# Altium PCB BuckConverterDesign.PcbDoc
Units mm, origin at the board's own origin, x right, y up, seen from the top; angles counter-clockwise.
Board outline 71.7 x 34.6 mm, 4 copper layers (Top Layer, IN-1, IN-2, Bottom Layer), stack 0.603 mm thick; 48 components, 33 nets, 182 pads, 54 vias.
Unrouted connection lines stored in the file: 113.
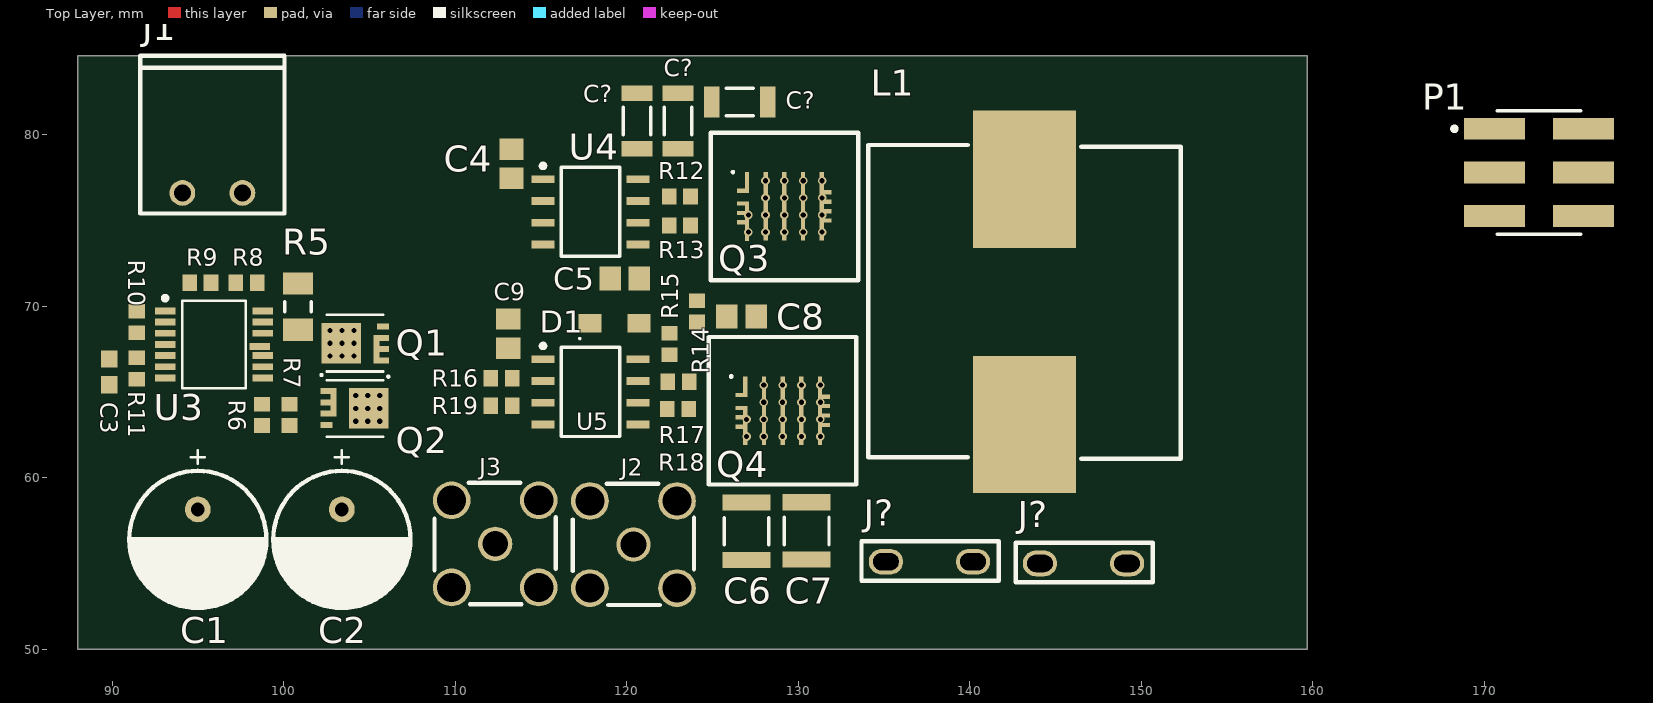
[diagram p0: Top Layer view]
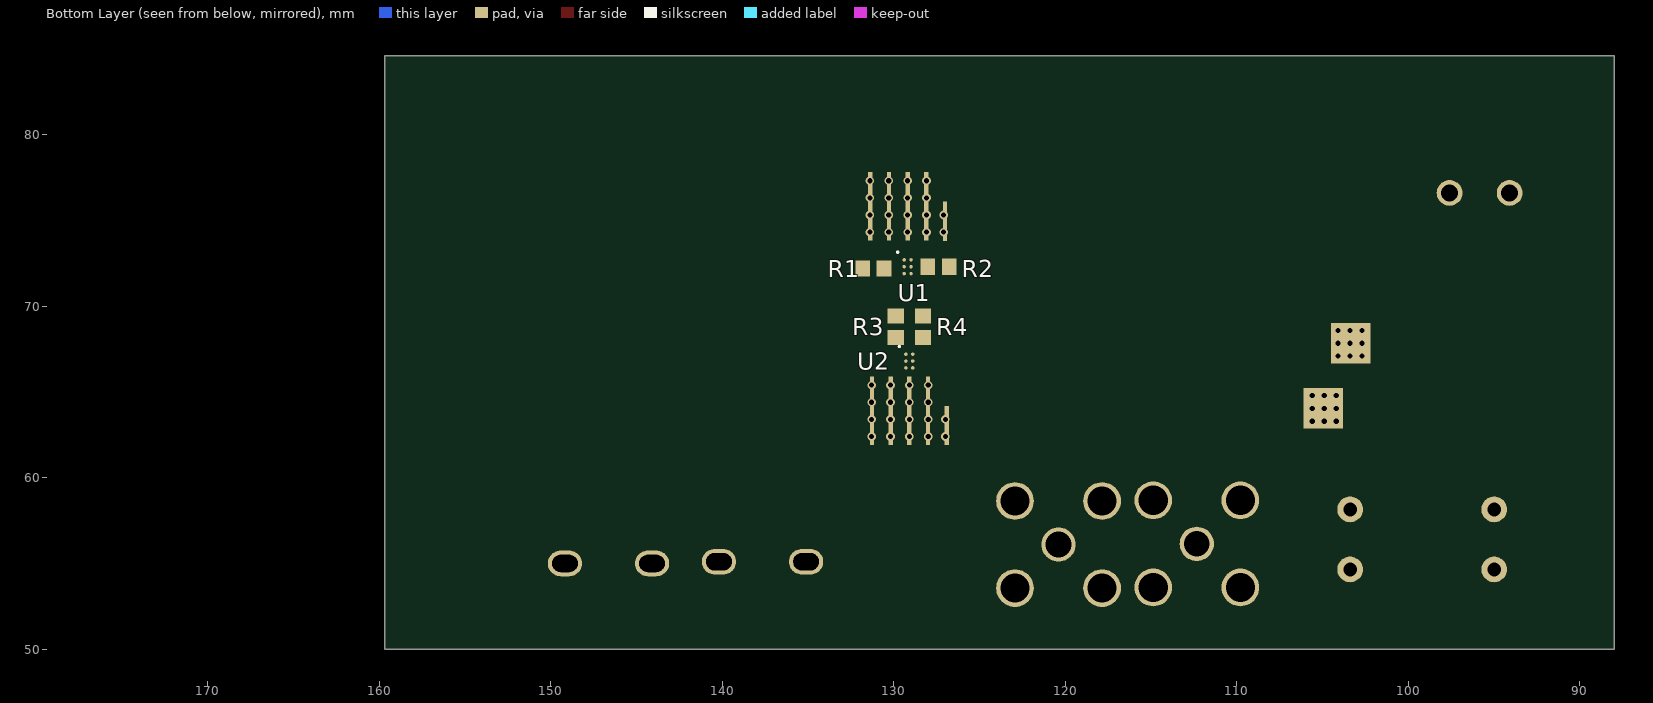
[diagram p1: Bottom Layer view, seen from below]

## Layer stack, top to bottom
Top Solder: solder mask 0.0102, Solder Resist, Dk 3.5
Top Layer: signal copper 0.035
Dielectric 2: prepreg 0.0711, PP-006, Dk 4.1
IN-1: signal copper 0.0356
Dielectric 1: dielectric 0.32, FR-4, Dk 4.8
IN-2: signal copper 0.0356
Dielectric 3: prepreg 0.0711, PP-006, Dk 4.1
Bottom Layer: signal copper 0.035
Bottom Solder: solder mask 0.0102, Solder Resist, Dk 3.5

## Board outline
88,50 159.7,50 159.7,84.6 88,84.6

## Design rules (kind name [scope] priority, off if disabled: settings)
AssemblyTestPointUsage [All] p1: isadvanced=TRUE
AssemblyTestpoint [All] p1: isadvanced=TRUE testpointundercomponent=TRUE minsize=1.016 maxsize=2.54 preferedsize=1.524 minholesize=0 maxholesize=1.016 preferedholesize=0.813 testpointgrid=0.025 usegrid=TRUE gridtolerance=0 allowsidetop=TRUE allowsidebottom=TRUE
Clearance Clearance_1 [All] p1: isadvanced=TRUE gap=0.15 ignorepadtopadclearanceinfootprint=FALSE
Clearance [All] p2: gap=0.254 ignorepadtopadclearanceinfootprint=FALSE ismatrix=TRUE
ComponentClearance [All] p1: isadvanced=TRUE gap=0.254 collisioncheckmode=3 verticalgap=0.254 showdistances=FALSE
FabricationTestPointUsage [All] p1: isadvanced=TRUE valid=0 allowmultiple=FALSE
FabricationTestpoint [All] p1: isadvanced=TRUE side=3 testpointundercomponent=TRUE minsize=1.016 maxsize=2.54 preferedsize=1.524 minholesize=0 maxholesize=1.016 preferedholesize=0.813 testpointgrid=0.025 allowsidetop=TRUE allowsidebottom=TRUE usegrid=TRUE gridtolerance=0
FanoutControl Fanout_BGA [IsBGA] p1: isadvanced=TRUE bgadir=Out bgaviamode=Centered fanoutstyle=Auto fanoutdirection=Alternating viagrid=0.025 // Fanout_BGA (Default Rule)
FanoutControl Fanout_LCC [IsLCC] p2: isadvanced=TRUE bgadir=Out bgaviamode=Centered fanoutstyle=Auto fanoutdirection=Alternating viagrid=0.025 // Fanout_LCC (Default Rule)
FanoutControl Fanout_SOIC [IsSOIC] p3: isadvanced=TRUE bgadir=Out bgaviamode=Centered fanoutstyle=Auto fanoutdirection=Alternating viagrid=0.025 // Fanout_SOIC (Default Rule)
FanoutControl Fanout_Small [(CompPinCount < 5)] p4: isadvanced=TRUE bgadir=Out bgaviamode=Centered fanoutstyle=Auto fanoutdirection=OutThenIn viagrid=0.025 // Fanout_Small (Default Rule)
FanoutControl Fanout_Default [All] p5: isadvanced=TRUE bgadir=Out bgaviamode=Centered fanoutstyle=Auto fanoutdirection=Alternating viagrid=0.025 // Fanout_Default (Default Rule)
Height [All] p1: isadvanced=TRUE minheight=0 maxheight=25.4 prefheight=12.7
HoleSize [All] p1: isadvanced=TRUE absolutevalues=TRUE maxlimit=20 minlimit=0.3 maxpercent=80.000 minpercent=20.000
HoleToHoleClearance [All] p1: isadvanced=TRUE gap=0.3 allowstackedmicrovias=TRUE
LayerPairs [All] p1: isadvanced=TRUE enforce=TRUE
MinimumSolderMaskSliver [All] p1: isadvanced=TRUE minsoldermaskwidth=0.15
NetAntennae [All] p1: isadvanced=TRUE netantennaetolerance=0
PasteMaskExpansion [All] p1: isadvanced=TRUE expansion=0.1 thpadusetoppaste=TRUE thpadusebottompaste=TRUE
PlaneClearance [All] p1: isadvanced=TRUE clearance=0.508
PlaneConnect [All] p1: isadvanced=TRUE planeconnectstyle=Relief reliefexpansion=0.508 reliefentries=4 reliefconductorwidth=0.254 reliefairgap=0.254
PolygonConnect PolygonConnect_5 [All vs IsNamedPolygon('SW_NODE_L01_P000')] p1: connectstyle=Direct reliefconductorwidth=0.254 reliefentries=4 polygonreliefangle="90 Angle" airgapwidth=0.254
PolygonConnect PolygonConnect_4 [All vs IsNamedPolygon('SW_NODE_L01_P000')] p2: connectstyle=Direct reliefconductorwidth=0.254 reliefentries=4 polygonreliefangle="90 Angle" airgapwidth=0.254
PolygonConnect PolygonConnect_3 [All vs IsNamedPolygon('NONET_L01_P000')] p3: thpad.connectstyle=Direct thpad.reliefconductorwidth=0.254 thpad.reliefentries=4 thpad.polygonreliefangle="90 Angle" thpad.airgapwidth=0.254 smdpad.connectstyle=Direct smdpad.reliefconductorwidth=0.254 smdpad.reliefentries=4 smdpad.polygonreliefangle="90 Angle" smdpad.airgapwidth=0.254 via.connectstyle=Relief via.reliefconductorwidth=0.254 via.reliefentries=4 via.polygonreliefangle="90 Angle" via.airgapwidth=0.254
PolygonConnect PolygonConnect_2 [All vs IsNamedPolygon('NONET_L01_P000')] p4: thpad.connectstyle=Direct thpad.reliefconductorwidth=0.254 thpad.reliefentries=4 thpad.polygonreliefangle="90 Angle" thpad.airgapwidth=0.254 smdpad.connectstyle=Direct smdpad.reliefconductorwidth=0.254 smdpad.reliefentries=4 smdpad.polygonreliefangle="90 Angle" smdpad.airgapwidth=0.254 via.connectstyle=Relief via.reliefconductorwidth=0.254 via.reliefentries=4 via.polygonreliefangle="90 Angle" via.airgapwidth=0.254
PolygonConnect PolygonConnect_1 [All vs IsNamedPolygon('NETQ3_1_L01_P001') Or IsNamedPolygon('NETQ4_1_L01_P002') Or IsNamedPolygon('NONET_L01_P000')] p5: connectstyle=Direct reliefconductorwidth=0.254 reliefentries=4 polygonreliefangle="90 Angle" airgapwidth=0.254
PolygonConnect [All] p6: connectstyle=Relief reliefconductorwidth=0.254 reliefentries=4 polygonreliefangle="90 Angle" airgapwidth=0.254
RoutingCorners [All] p1: isadvanced=TRUE cornerstyle=45-Degree minsetback=2.54 maxsetback=2.54
RoutingPriority [All] p1: isadvanced=TRUE routingpriority=0
RoutingTopology RoutingTopology_1 [All] p1: isadvanced=TRUE topology=Daisy_Balanced
RoutingVias RoutingViaStyle_1 [All] p1: isadvanced=TRUE holewidth=0.3 width=0.5 viastyle="Through Hole" minholewidth=0.3 minwidth=0.5 maxholewidth=10 maxwidth=20
RoutingVias [All] p2: holewidth=0.711 width=1.27 viastyle="Through Hole" minholewidth=0.711 minwidth=1.27 maxholewidth=0.711 maxwidth=1.27
ShortCircuit [All] p1: isadvanced=TRUE allowed=FALSE
SilkToSilkClearance [All] p1: isadvanced=TRUE silktosilkclearance=0.15
SilkToSolderMaskClearance [IsPad] p1: isadvanced=TRUE minsilkscreentomaskgap=0.15 clearancetoexposedcopper=TRUE
SolderMaskExpansion [All] p1: isadvanced=TRUE expansion=0.102 istentingtop=TRUE
SupplyNets "Schematic Supply Nets_12" [InNet('3V3')] p1: voltage=0.000
SupplyNets "Schematic Supply Nets_11" [InNet('VIN')] p2: voltage=0.000
SupplyNets "Schematic Supply Nets_10" [InNet('OUT')] p3: voltage=0.000
SupplyNets "Schematic Supply Nets_9" [InNet('5V')] p4: voltage=0.000
SupplyNets "Schematic Supply Nets_2" [InNet('GND')] p5: voltage=0.000
SupplyNets "Schematic Supply Nets_1" [InNet('SW Node')] p6: voltage=0.000
UnRoutedNet [All] p1: isadvanced=TRUE
UnpouredPolygon [All] p1 off: isadvanced=TRUE
Width MaxMinWidth_1 [All] p1: isadvanced=TRUE maxlimit=10 minlimit=0.15 preferedwidth=0.3 minimp=50.000000 maximp=50.000000 favimp=50.000000
3 further rules are at their usual default settings.

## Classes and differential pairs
component class [06]TemperatureSense: R1 R2 R3 R4 U1 U2
component class [00]Connectors: J2 J3 J? P1
component class [05]BuckConverter: C4 C5 C6 C7 C8 C9 C? D1 L1 Q3 Q4 R12 R13 R14 R15 R16 R17 R18 R19 U4 U5
component class [02]PowerProtections: C1 C2 C3 J1 Q1 Q2 R5 R6 R7 R8 R9 R10 R11 U3

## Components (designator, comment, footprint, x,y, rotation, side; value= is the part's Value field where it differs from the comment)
C1 "AlPolTHT 100 µF 63V 0603 X7R ±10%" 107AVG063MFBJ 95,56.4 r270 top
C2 "AlPolTHT 100 µF 63V 0603 X7R ±10%" 107AVG063MFBJ 103.4,56.4 r270 top
C3 "CerSMD 10nF 16V 0603 X7R ±10%" CAPC1608X09N 89.844,66.168 r270 top
C4 "CerSMD 100nF 16V 0805 X7R ±10%" CAPC2012X09N 113.3,78.3 r90 top
C5 "CerSMD 220nF 50V 0805 X7R ±10%" CAPC2012X09N 119.9,71.6 r0 top
C6 "CerSMD 3.3µF 100V 1210 X7S ±10%" CAPC3225X28N 127,56.875 r90 top
C7 "CerSMD 3.3µF 100V 1210 X7S ±10%" CAPC3225X28N 130.5,56.9 r90 top
C8 "CerSMD 2.2 µF 16V 0805 X7R ±10%" CAPC2012X09N 126.7,69.4 r0 top
C9 "CerSMD 100nF 16V 0805 X7R ±10%" CAPC2012X09N 113.1,68.4 r90 top
C? "CerSMD 10µF 100V 1210 X6S ±10%" CAPC3216X18N 126.6,81.9 r0 top
C? "CerSMD 10µF 100V 1210 X6S ±10%" CAPC3216X18N 123,80.8 r270 top
C? "CerSMD 10µF 100V 1210 X6S ±10%" CAPC3216X18N 120.6,80.8 r270 top
D1 "MBR1H100SFT3G" SODFL360X95-2N 119.3,69 r180 top
J1 "1844210" 1844210#1 91.65,75.4 r0 top
J2 "RF2-19A-T-00-50-G" RF2-19A-T-00-50-G#1 117.86,53.56 r0 top
J3 "RF2-19A-T-00-50-G" RF2-19A-T-00-50-G#2 109.8,53.6 r0 top
J? "726386-2" 1844210#2 140.2,55.1 r180 top
J? "726386-2" 1844210#2 149.18,55 r180 top
L1 "IndSMD Shielded 7.6 µH 20A 20.5 3.75 mOhm" 7443557760 134.1,61.2 r0 top
P1 "5-146130-2" TECO-5-146130-2_V 173.2,77.8 r270 top
Q1 "BSZ040N06LS5ATMA1" PG-TSDSON-8-FL 105.808,66.191 r90 top
Q2 "BSZ040N06LS5ATMA1" PG-TSDSON-8-FL 102.508,65.691 r270 top
Q3 "IGC019S06S1XTMA1" IGC019S06S1XTMA1 126.7,77.317 r270 top
Q4 "IGC019S06S1XTMA1" IGC019S06S1XTMA1 126.6,65.4 r270 top
R1 "SMDRes 10K 0603 %1 0.1W" RESC1508X06N 131.2,72.2 r0 bottom
R2 "SMDRes 10K 0603 %1 0.1W" RESC1508X06N 127.4,72.3 r180 bottom
R3 "SMDRes 10K 0603 %1 0.1W" RESC1508X06N 129.9,68.8 r90 bottom
R4 "SMDRes 10K 0603 %1 0.1W" RESC1508X06N 128.3,68.8 r90 bottom
R5 "SMDRes 5 mOhm 1206 %1 1W" RESC3116X10N 100.844,69.968 r270 top
R6 "SMDRes 470K 0603 %1 0.1W" RESC1508X06N 98.744,63.668 r270 top
R7 "SMDRes 470K 0603 %1 0.1W" RESC1508X06N 100.344,63.668 r270 top
R8 "SMDRes 374K 0603 %1 0.1W" RESC1508X06N 97.844,71.368 r180 top
R9 "SMDRes 1.82K 0603 %1 0.1W" RESC1508X06N 95.144,71.368 r0 top
R10 "SMDRes 47K 0603 %1 0.1W" RESC1508X06N 91.444,69.068 r90 top
R11 "SMDRes 10K 0603 %1 0.1W" RESC1508X06N 91.444,66.368 r270 top
R12 "SMDRes 10 Ohm 0603 %1 0.1W" RESC1508X06N 123.1,76.4 r0 top
R13 "SMDRes 2 Ohm 0603 %1 0.1W" RESC1508X06N 123.1,74.7 r0 top
R14 "SMDRes 10 Ohm 0603 %1 0.1W" RESC1508X06N 124.1,69.7 r90 top
R15 "SMDRes 2.2 Ohm 0603 %1 0.1W" RESC1508X06N 122.5,67.8 r90 top
R16 "SMDRes 33 kOhm 0603 %1 0.1W" RESC1508X06N 112.7,65.8 r0 top
R17 "SMDRes 10 Ohm 0603 %1 0.1W" RESC1508X06N 123.025,65.6 r0 top
R18 "SMDRes 2 Ohm 0603 %1 0.1W" RESC1508X06N 123,64 r0 top
R19 "SMDRes 33 kOhm 0603 %1 0.1W" RESC1508X06N 112.7,64.2 r0 top
U1 "TMP119AIYBGR" BGA6C40P2X3_95X149X52 129.2,72.3 r180 bottom
U2 "TMP119AIYBGR" BGA6C40P2X3_95X149X52 129.1,66.8 r180 bottom
U3 "TPS2492PWR" TSOP65P640X120-14L 95.944,67.768 r0 top
U4 "1EDB7275FXUMA1" SOIC127P600X175-8N 117.9,75.5 r0 top
U5 "1EDB7275FXUMA1" SOIC127P600X175-8N 117.9,65 r0 top

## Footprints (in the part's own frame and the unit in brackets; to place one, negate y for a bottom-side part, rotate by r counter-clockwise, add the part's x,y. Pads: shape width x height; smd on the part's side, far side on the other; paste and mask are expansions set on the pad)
107AVG063MFBJ [mm] "8mm Diameter  13..5mm Height 3.5mm Pitch"
  round 1.5 hole 0.8 mask+0: 1(-1.75,0) 2(1.75,0)
  silkscreen extent -5.2,-4 4,4, body extent -4,-4 4,4, height 13.85
1844210#1 [mm]
  round 1.5 hole 1: 1(2.45,1.2) 2(5.95,1.2)
  silkscreen extent 0,0 8.4,9.2, body extent 0,0 8.4,9.2, height 7.25
1844210#2 [mm]
  oval 2x1.5 hole 1 slot 1.5 at 0 deg: 1(0,0) 1(5.08,0)
  silkscreen extent -1.5,-1.2 6.5,1.1, body extent -1.5,-0.4 6.5,0.4, height 10.1
7443557760 [mm]
  rect 6x8 smd mask+0: 1(9.1,16.2) 2(9.1,1.9)
  silkscreen extent 0,-0.1 18.2,18.2, body extent 0,-0.1 18.2,18.2, height 8.85
BGA6C40P2X3_95X149X52 [mm] "BGA, 6-Leads, Body 0.95x1.49mmx0.53mm, Pitch 0.40mm"
  round 0.2 smd mask+0: A1(-0.2,0.4) A2(0.2,0.4) B1(-0.2,0) B2(0.2,0) C1(-0.2,-0.4) C2(0.2,-0.4)
  silkscreen extent -0.63,0.8 -0.53,0.9, body extent -0.48,-0.74 0.48,0.74, height 0.53
CAPC1608X09N [mm] "Chip Capacitor, 2-Leads, Body 1.60x0.80mm, IPC Medium Density"
  rect 1x0.95 smd mask+0: 1(-0.75,0) 2(0.75,0)
  body extent -0.85,-0.45 0.85,0.45, height 0.9
CAPC2012X09N [mm] "Chip Capacitor, 2-Leads, Body 2.00x1.25mm, IPC Medium Density"
  rect 1.25x1.4 smd mask+0: 1(-0.85,0) 2(0.85,0)
  body extent -1.07,-0.67 1.07,0.67, height 0.9
CAPC3216X18N [mm] "Chip Capacitor, 2-Leads, Body 3.20x1.60mm, IPC Medium Density"
  rect 0.9x1.8 smd: 1(-1.625,0) 2(1.625,0)
  silkscreen extent -0.8,-0.8 0.8,0.8, body extent -1.7,-0.9 1.7,0.9, height 1.8
CAPC3225X28N [mm] "Chip Capacitor, 2-Leads, Body 3.20x2.50mm, IPC Medium Density"
  rect 0.95x2.8 smd mask+0: 1(-1.675,0) 2(1.675,0)
  silkscreen extent -0.8,-1.3 0.8,1.3, body extent -1.8,-1.4 1.8,1.4, height 2.8
IGC019S06S1XTMA1 [mm] "PG-TSON-6-2"
  rect 1.2x0.25 smd mask+0: 1(0.107,0.325)
  rect 0.25x0.7 smd mask+0: 1(0.582,0.09) 5(0.675,4.91) 5(1.225,4.91) 5(1.775,4.91) 5(2.325,4.91) 6(1.332,0.09) 6(1.882,0.09) 6(2.432,0.09)
  rect 4x0.25 smd mask+0: 2(1.5,1.412) 3(1.5,2.5) 4(1.5,3.587) 5(1.5,4.675)
  rect 4x0.25 smd far side mask+0: 2(1.5,1.412) 3(1.5,2.5) 4(1.5,3.587) 5(1.5,4.675)
  rect 2.3x0.25 smd mask+0: 6(2.357,0.325)
  rect 2.3x0.25 smd far side mask+0: 6(2.357,0.325)
  silkscreen extent -0.56,-0.56 -0.44,-0.44, body extent 0,0 3,5, height 1.04
PG-TSDSON-8-FL [mm]
  rect 0.35x0.7 smd mask+0: 1(0.65,0) 1(1.3,0) 1(1.95,0) 2(2.625,0)
  rect 1.65x0.35 smd mask+0: 1(1.3,0.4)
  rect 2.35x2.3 smd mask+0: 3(1.65,2.45)
  rect 2.35x2.3 smd far side: 3(1.65,2.45)
  silkscreen extent -0.35,-0.35 3.3,3.3, body extent 0,0 3.3,3.3, height 1.11
RESC1508X06N [mm] "Chip Resistor, 2-Leads, Body 1.55x0.80mm, IPC Medium Density"
  rect 0.85x0.95 smd mask+0: 1(-0.625,0) 2(0.625,0)
  body extent -0.85,-0.48 0.85,0.48, height 0.6
RESC3116X10N [mm] "Chip Resistor, 2-Leads, Body 3.10x1.55mm, IPC Medium Density"
  rect 1.3x1.75 smd mask+0: 1(-1.35,0) 2(1.35,0)
  silkscreen extent -0.3,-0.77 0.3,0.77, body extent -1.65,-0.87 1.65,0.87, height 0.95
RF2-19A-T-00-50-G#1 [mm]
  round 2 hole 1.5 mask+0: 1(2.54,2.54)
  round 2.2 hole 1.7: Shield(0,0)
  round 2.2 hole 1.7 mask+0: Shield(0,5.08) Shield(5.08,0) Shield(5.08,5.08)
  silkscreen extent -1,-0.98 6.07,6.1, body extent -0.96,-0.96 6.04,6.04, height 9.6
RF2-19A-T-00-50-G#2 [mm]
  round 2 hole 1.5 mask+0: 1(2.54,2.54)
  round 2.2 hole 1.7 mask+0: Shield(0,0) Shield(0,5.08) Shield(5.08,0) Shield(5.08,5.08)
  silkscreen extent -1,-0.98 6.07,6.1, body extent -0.96,-0.96 6.04,6.04, height 9.6
SODFL360X95-2N [mm] "SODFL, 2-Leads, Body 1.65x3.60mm, IPC Medium Density"
  rect 1.35x1.1 smd mask+0: 1(-1.425,0) 2(1.425,0)
  silkscreen extent 1.98,0.84 2.08,0.94, body extent -1.8,-0.9 1.8,0.9, height 0.95
SOIC127P600X175-8N [mm] "SOIC, 8-Leads, Body 5.00x4.00mm, Pitch 1.27mm, IPC Medium Density"
  rect 1.35x0.45 smd mask+0: 1(-2.775,1.905) 2(-2.775,0.635) 3(-2.775,-0.635) 4(-2.775,-1.905) 5(2.775,-1.905) 6(2.775,-0.635) 7(2.775,0.635) 8(2.775,1.905)
  silkscreen extent -2.9,-2.6 1.7,2.8, body extent -3,-2.6 3,2.6, height 1.75
TECO-5-146130-2_V [mm] "Header, 6-Leads, Body 7.21x4.88mm, Pitch 2.54mm"
  rect 1.27x3.56 smd: 1(-2.54,-2.605) 2(-2.54,2.605) 3(0,-2.605) 4(0,2.605) 5(2.54,-2.605) 6(2.54,2.605)
  silkscreen extent -3.6,-5.06 3.6,2.44, body extent -3.61,-3.77 3.61,3.64, height 9.74
TSOP65P640X120-14L [mm] "TSOP, 14-Leads, Body 5.00x4.40mm, Pitch 0.65mm, IPC High Density"
  rect 1.2x0.4 smd mask+0: 1(-2.85,1.95) 2(-2.85,1.3) 3(-2.85,0.65) 4(-2.85,0) 5(-2.85,-0.65) 6(-2.85,-1.3) 7(-2.85,-1.95) 8(2.85,-1.95) 9(2.85,-1.3) 10(2.85,-0.65) 11(2.667,-0.127) 12(2.85,0.65) 13(2.85,1.3) 14(2.85,1.95)
  silkscreen extent -2.97,-2.55 1.85,2.82, body extent -3.2,-2.5 3.2,2.5, height 1.21

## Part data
C1 C2: library part CMP-00002-4, "Ceramic Capacitor SMD 100 µF 63V 0603 X7R ±10%", Digi-Key Part Number=1572-1656-ND, Manufacturer="Cornell Dubilier Knowles", Manufacturer Number=107AVG063MFBJ, Mouser Part Number=598-107AVG063MFBJ, Package=0603, Temperature="-55°C up to 125°C", Temperature Coefficient=X7R, Tolerance=±10%, Voltage=63V
C3: library part CMP-00001-3, "Ceramic Capacitor SMD  10nF 16V 0603 X7R ±10%", Digi-Key Part Number=1276-CL10B103KO8WPNCCT-ND, Manufacturer="Samsung Electro-Mechanics", Manufacturer Number=CL10B103KO8WPNC, Mouser Part Number=187-CL10B103KO8WPNC, Package=0603, Temperature="-55°C up to 125°C", Temperature Coefficient=X7R, Tolerance=±10%, Voltage=16V
C4 C9: library part CMP-00013-1, "Ceramic Capacitor SMD 100nF 10V 0805 X7R ±10%", Digi-Key Part Number=732-8026-1-ND, Farnell Part Number=2534051, Manufacturer="Würth Elektronik", Manufacturer Number=885012207016, Mouser Part Number=710-885012207016, Package=0603, Temperature="-55°C up to 125°C", Temperature Coefficient=X7R, Tolerance=±10%, Voltage=10V
C5: library part CMP-00016-1, "Ceramic Capacitor SMD 220nF 50V 0805 X7R ±10%", Digi-Key Part Number=490-1670-1-ND, Manufacturer="Murata Electronics", Manufacturer Number=GRM21BR71H224KA01L, Mouser Part Number=81-GRM40X7R224K050AL, Package=0805, Temperature="-55°C up to 125°C", Temperature Coefficient=X7R, Tolerance=±10%, Voltage=10V
C6 C7: library part CMP-00010-1, "Ceramic Capacitor SMD 3.3µF 100V 1210 X7S ±10%", Digi-Key Part Number=445-5209-1-ND, Manufacturer="Samsung Electro-Mechanics", Manufacturer Number=C3225X7S2A335K200AB, Mouser Part Number=810-C3225X7S2A335K, Package=0603, Temperature="-55°C up to 125°C", Temperature Coefficient=X7R, Tolerance=±10%, Voltage=16V
C8: library part CMP-00014-1, "Ceramic Capacitor SMD 2.2 µF 16V 0805 X7R ±10%", Digi-Key Part Number=445-1420-1-ND, Farnell Part Number=1907345, Manufacturer="TDK Corporation", Manufacturer Number=C2012X7R1C225K125AB, Mouser Part Number=810-C2012X7R1C225K, Package=0805, Temperature="-55°C up to 125°C", Temperature Coefficient=X7R, Tolerance=±10%, Voltage=16V
C? C? C?: library part CMP-000078-1, "Ceramic Capacitor SMD 10µF 100V 1210 X6S ±10%", Digi-Key Part Number=C3216X6S2A106K160AC, Manufacturer="TDK Corporation", Mouser Part Number=810-C3216X6S2A106K16, Package=0603, Temperature="-55°C up to 125°C", Temperature Coefficient=X7R, Tolerance=±10%, Voltage=16V
D1: library part CMP-00020-2
J1: library part CMP-00023-1, "12A 2-Pos, Right Angle"
J2 J3: library part CMP-00025-2, "Rf Sma Connector"
J? J?: library part CMP-00026-1
L1: library part CMP-00011-1, "Inductor SMD Shielded 7.6 µH 20A 20.5 3.75 mOhm"
P1: library part CMP-002-00018-2, "Male Header, Pitch 2.54 mm, 2 x 3 Position, Height 8.13 mm, -65 to 125 degC, RoHS, Tube", Manufacturer="TE Connectivity", Max Operating Temperature=125°C, Min Operating Temperature=-65°C, Package Description="Male Header, Pitch 2.54 mm, 2 x 3 Position, Height 8.13 mm"
Q1 Q2: library part CMP-00004-1, "N-MOS 60V 17A (Ta) 101A (Tc)"
Q3 Q4: library part CMP-00009-4, "GaNFET N-Ch - 60V - 27A (Ta), 99A (Tc)", Digi-Key Part Number=448-IGC019S06S1XTMA1CT-ND, Drive Voltage=5V, Farnell Part Number=4680815, Manufacturer="Infineon Technologies", Mouser Part Number=726-IGC019S06S1XTMA1, Operating Temperature="-40°C up to 150°C (TJ)", Package=PG-TSON-6-2
R1 R2 R3 R4: library part CMP-00001-1-2, "Res Thick Film 0603 10K Ohm 1% 0.1W(1/10W) ±100ppm/C Pad SMD T/R Automotive AEC-Q200", Digi-Key Part Number=RMCF0603FT10K0CT-ND, Manufacturer="Stackpole Electronics Inc", Manufacturer Number=RMCF0603FT10K0, Mouser Part Number=708-RMCF0603FT10K0, Package=0603, Power=0.1W, Temperature="-55°C up to 155°C", Tolerance=±1%
R5: library part CMP-00007-2, "5 mOhms ±1% 1W Chip Resistor 1206 (3216 Metric) Automotive AEC-Q200, Current Sense, Moisture Resistant Metal Foil", Digi-Key Part Number=CSRF1206FT5L00CT-ND, Manufacturer="Stackpole Electronics Inc", Manufacturer Number=CSRF1206FT5L00, Mouser Part Number=708-CSRF1206FT5L00, Package=1206, Power=1W, Temperature="-55°C up to 170°C", Tolerance=±1%
R6 R7: library part CMP-00006-1, "Res Thick Film 0603 470K Ohm 1% 0.1W(1/10W) ±100ppm/C Pad SMD T/R Automotive AEC-Q200", Digi-Key Part Number=RMCF0603FT470KCT-ND, Manufacturer="Stackpole Electronics Inc", Manufacturer Number=RMCF0603FT470K, Mouser Part Number=708-RMCF0603FT470K, Package=0603, Power=0.1W, Temperature="-55°C up to 155°C", Tolerance=±1%
R8: library part CMP-00005-2, "Res Thick Film 0603 374K Ohm 1% 0.1W(1/10W) ±100ppm/C Pad SMD T/R Automotive AEC-Q200", Digi-Key Part Number=RMCF0603FT374KCT-ND, Manufacturer="Stackpole Electronics Inc", Manufacturer Number=RMCF0603FT374K, Mouser Part Number=708-RMCF0603FT374K, Package=0603, Power=0.1W, Temperature="-55°C up to 155°C", Tolerance=±1%
R9: library part CMP-00003-2, "Res Thick Film 0603 1.82K Ohm 1% 0.1W(1/10W) ±100ppm/C Pad SMD T/R Automotive AEC-Q200", Digi-Key Part Number=RMCF0603FT1K82CT-ND, Manufacturer="Stackpole Electronics Inc", Manufacturer Number=RMCF0603FT1K82, Mouser Part Number=708-RMCF0603FT1K82, Package=0603, Power=0.1W, Temperature="-55°C up to 155°C", Tolerance=±1%
R10: library part CMP-00008-1, "Res Thick Film 0603 47K Ohm 1% 0.1W(1/10W) ±100ppm/C Pad SMD T/R Automotive AEC-Q200", Digi-Key Part Number=RMCF0603FT47K0CT-ND, Manufacturer="Stackpole Electronics Inc", Manufacturer Number=RMCF0603FT47K0, Mouser Part Number=708-RMCF0603FT47K0, Package=0603, Power=0.1W, Temperature="-55°C up to 155°C", Tolerance=±1%
R11: library part CMP-00001-1-1, "Res Thick Film 0603 10K Ohm 1% 0.1W(1/10W) ±100ppm/C Pad SMD T/R Automotive AEC-Q200", Digi-Key Part Number=RMCF0603FT10K0CT-ND, Manufacturer="Stackpole Electronics Inc", Manufacturer Number=RMCF0603FT10K0, Mouser Part Number=708-RMCF0603FT10K0, Package=0603, Power=0.1W, Temperature="-55°C up to 155°C", Tolerance=±1%
R12 R14 R17: library part CMP-00017-1, "Res Thick Film 0603 10 Ohm Ohm 1% 0.1W(1/10W) ±100ppm/C Pad SMD T/R Automotive AEC-Q200", Digi-Key Part Number=RMCF0603FT10R0CT-ND, Manufacturer="Stackpole Electronics Inc", Manufacturer Number=RMCF0603FT10R0, Mouser Part Number=708-RMCF0603FT10R0, Package=0603, Power=0.1W, Temperature="-55°C up to 155°C", Tolerance=±1%
R13 R18: library part CMP-00019-1, "Res Thick Film 0603 2 Ohm Ohm 1% 0.1W(1/10W) ±100ppm/C Pad SMD T/R Automotive AEC-Q200", Digi-Key Part Number=RMCF0603FT2R00CT-ND, Manufacturer="Stackpole Electronics Inc", Manufacturer Number=RMCF0603FT2R00, Mouser Part Number=708-RMCF0603FT2R00, Package=0603, Power=0.1W, Temperature="-55°C up to 155°C", Tolerance=±1%
R15: library part CMP-00015-1, "Res Thick Film 0603 2.2 Ohm Ohm 1% 0.1W(1/10W) ±100ppm/C Pad SMD T/R Automotive AEC-Q200", Digi-Key Part Number=RMCF0603FT2R20CT-ND, Manufacturer="Stackpole Electronics Inc", Manufacturer Number=RMCF0603FT2R20, Mouser Part Number=708-RMCF0603FT2R20, Package=0603, Power=0.1W, Temperature="-55°C up to 155°C", Tolerance=±1%
R16 R19: library part CMP-00018-1, "Res Thick Film 0603 33 kOhm Ohm 1% 0.1W(1/10W) ±100ppm/C Pad SMD T/R Automotive AEC-Q200", Digi-Key Part Number=RMCF0603FT33K0CT-ND, Manufacturer="Stackpole Electronics Inc", Manufacturer Number=RMCF0603FT33K0, Mouser Part Number=708-RMCF0603FT33K0, Package=0603, Power=0.1W, Temperature="-55°C up to 155°C", Tolerance=±1%
U1 U2: library part CMP-00021-1, "Temperature Sensor"
U3: library part CMP-00000-1, "eFuses - External MOSFETs - 9V-80V", Digi-Key Part Number=296-39373-1-ND, Manufacturer="Texas Instruments", Mouser Part Number=595-TPS2492PWR, Package=14-TSSOP, Temperature Rating="-40°C up to 125°C", Voltage Rating="9V up to 80V"
U4 U5: library part CMP-00012-1

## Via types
v1: diameter 0.5, hole 0.3, Top Layer to Bottom Layer, tented both sides, 54 vias

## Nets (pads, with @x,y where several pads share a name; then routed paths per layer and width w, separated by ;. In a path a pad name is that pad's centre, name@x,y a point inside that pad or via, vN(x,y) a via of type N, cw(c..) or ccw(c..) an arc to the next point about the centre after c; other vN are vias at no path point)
3V3: C4.1 C9.1 P1.6 R1.2 R2.2 R3.2 R4.2 R6.2 R7.2 R14.2 U1.B1 U2.B1 U4.1 U5.1
5V: C5.1 D1.2 P1.5 U4.8
GND: C1.2 C2.2 C3.2 C4.2 C6.2 C7.2 C8.2 C9.2 C?.2 J1.1 J2.Shield J3.Shield J?.1@144.1,55 J?.1@149.18,55 Q4.3 Q4.5 Q4.6 R11.2 U1.B2 U1.C1 U2.B2 U2.C1 U3.7 U4.4 U5.4 U5.5
  other v1: 127,62.4 129.1,62.4 131.3,62.4 127,63.4 129.1,63.4 131.3,63.4 129.1,64.4 131.3,64.4 129.1,65.4 131.3,65.4
NetC3_1: C3.1 U3.4
NetC8_1: C8.1 R14.1 R15.1 U5.8
NetD1_1: D1.1 R15.2
NetJ1_2: J1.2 R5.1 R8.1 U3.14
NetJ2_1: J2.1 P1.1 R16.1 U4.3
NetJ3_1: J3.1 P1.3 R19.1 U4.2
NetP1_2: P1.2 R1.1 R3.1 U1.A1 U2.A1
NetP1_4: P1.4 R2.1 R4.1 U1.A2 U2.A2
NetQ1_1: Q1.1 Q2.1 U3.11
NetQ1_2: Q1.2 Q2.2 U3.12
NetQ1_3: Q1.3 R5.2 U3.13
  other v1: 102.708,67.091 103.408,67.091 104.108,67.091 102.708,67.841 103.408,67.841 104.108,67.841 102.708,68.591 103.408,68.591 104.108,68.591
NetQ3_1: Q3.1 R12.2 R13.2
NetQ4_1: Q4.1 R17.2 R18.2
NetR6_1: R6.1 U3.8
NetR7_1: R7.1 U3.9
NetR8_2: R8.2 R9.2 U3.1
NetR9_1: R9.1 R11.1 U3.5
NetR10_1: R10.1 U3.3
NetR10_2: R10.2 U3.2
NetR12_1: R12.1 U4.7
NetR13_1: R13.1 U4.6
NetR16_2: R16.2 U5.2
NetR17_1: R17.1 U5.7
NetR18_1: R18.1 U5.6
NetR19_2: R19.2 U5.3
NetU1_C2: U1.C2
NetU2_C2: U2.C2
OUT: C6.1 C7.1 J?.1@135.12,55.1 J?.1@140.2,55.1 L1.2
"SW Node": C5.2 L1.1 Q3.3 Q3.5 Q3.6 Q4.2 Q4.4 U4.5
  other v1: 128,62.4 130.2,62.4 128,63.4 130.2,63.4 128,64.4 130.2,64.4 128,65.4 130.2,65.4 127.1,74.317 129.2,74.317 131.4,74.317 127.1,75.317 129.2,75.317 131.4,75.317 129.2,76.317 131.4,76.317 129.2,77.317 131.4,77.317
VIN: C1.1 C2.1 C?.1 Q2.3 Q3.2 Q3.4
  other v1: 104.208,63.291 104.908,63.291 105.608,63.291 104.208,64.041 104.908,64.041 105.608,64.041 104.208,64.791 104.908,64.791 105.608,64.791 128.1,74.317 130.3,74.317 128.1,75.317 130.3,75.317 128.1,76.317 130.3,76.317 128.1,77.317 130.3,77.317
pads on no net: U3.6 U3.10

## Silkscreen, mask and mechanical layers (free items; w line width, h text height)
Top Overlay:
  lines w0.254: 124.8,63.594 124.8,68.2 128.8,68.2 ; 124.8,63.6 124.8,59.6 128.8,59.6 ; 124.9,75.511 124.9,80.117 128.9,80.117 ; 124.9,75.517 124.9,71.517 128.9,71.517 ; 128.794,59.6 133.4,59.6 133.4,64.206 ; 128.794,68.2 133.4,68.2 133.4,64.2 ; 128.894,71.517 133.5,71.517 133.5,76.122 ; 128.894,80.117 133.5,80.117 133.5,76.117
